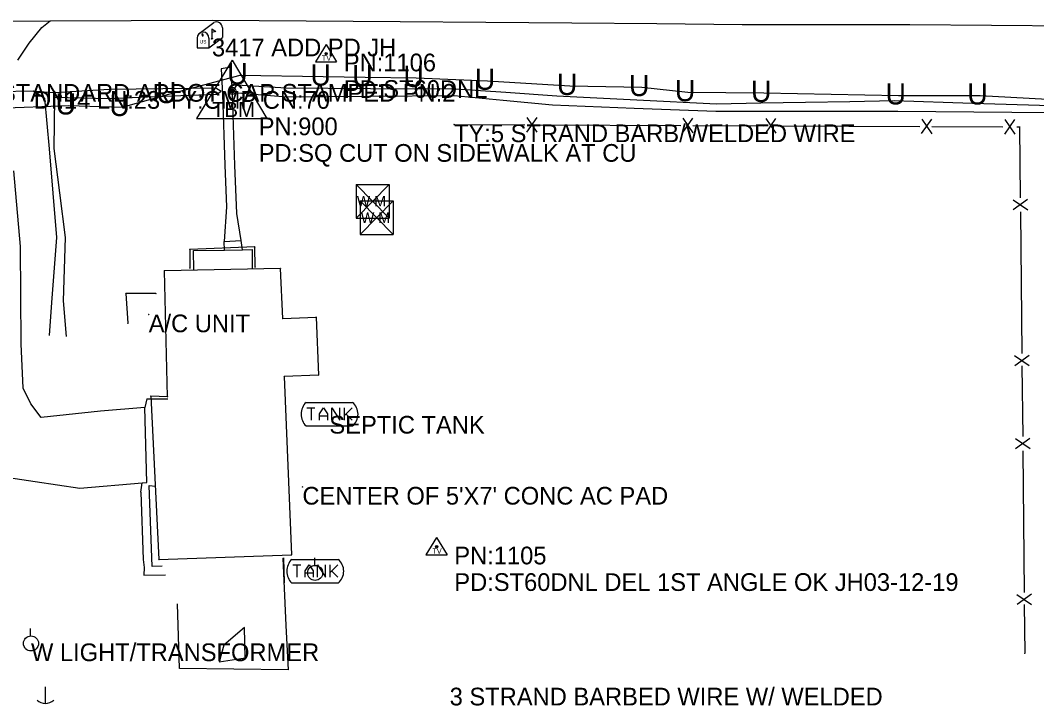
# Model space of a CAD drawing. Extents: x 1939239 to 1943096, y 531224 to 537447.
# Drawn here: x 1940013.5 to 1940300.4, y 534565.5 to 534758.9 of the extents above; entities that cross this region are included whole.
import ezdxf

# ---------------------------------------------------------------- set-up
doc = ezdxf.new("R2010")
doc.units = 0
for name, color, linetype in [('Default', 7, 'Continuous'), ('S_BUILDING', 7, 'Continuous'), ('S_DITCHLINE', 7, 'Continuous'), ('S_DRG_PT_SYM', 7, 'Continuous'), ('S_EDGE_BITUMINOUS', 7, 'Continuous'), ('S_EDGE_CONCRETE', 7, 'Continuous'), ('S_EDGE_PAVEMENT', 7, 'Continuous'), ('S_FENCE', 7, 'Continuous'), ('S_FENCE_ANNOT', 7, 'Continuous'), ('S_MAILBOX', 7, 'Continuous'), ('S_MAILBOX_ANNOT', 7, 'Continuous'), ('S_MISC_STRUCTURES_ANNOT', 7, 'Continuous'), ('S_MSC_PT_SYM', 7, 'Continuous'), ('S_PRIMARY_CTL', 7, 'Continuous'), ('S_PRIMARY_CTL_ANNOT', 7, 'Continuous'), ('S_SECONDARY_CTL', 7, 'Continuous'), ('S_SECONDARY_CTL_ANNOT', 7, 'Continuous'), ('S_SIDE_DRAIN', 7, 'Continuous'), ('S_SIDE_DRAIN_ANNOT', 7, 'Continuous'), ('S_STR_PT_SYM', 7, 'Continuous'), ('S_SURVEY_TEXT_ANNOT', 7, 'Continuous'), ('S_TANK', 7, 'Continuous'), ('S_TANK_ANNOT', 7, 'Continuous'), ('S_UNDERGROUND_CABLE', 7, 'Continuous'), ('S_UTILITY_POLE', 7, 'Continuous'), ('S_UTILITY_POLE_ANNOT', 7, 'Continuous'), ('S_WATER_UTILITIES', 7, 'Continuous')]:
    doc.layers.add(name, color=color, linetype=linetype)

msp = doc.modelspace()

# ---------------------------------------------------------------- linework, layer by layer
at = {"layer": 'S_BUILDING'}
for p, q in [((1940079.65, 534694.96), (1940061.33, 534694.27)), ((1940061.33, 534694.27), (1940061.34, 534688.97)), ((1940079.77, 534689.27), (1940079.65, 534694.96)), ((1940086.9, 534688.86), (1940054.18, 534688.24)), ((1940087.56, 534674.72), (1940086.9, 534688.86)), ((1940055.01, 534652.68), (1940054.18, 534688.24)), ((1940087.56, 534674.72), (1940097.03, 534675.12)), ((1940097.03, 534675.12), (1940097.62, 534658.8)), ((1940097.62, 534658.8), (1940088, 534658.34)), ((1940088, 534658.34), (1940090.03, 534608.07)), ((1940055.01, 534652.68), (1940050.31, 534652.79)), ((1940050.31, 534652.79), (1940052.6, 534606.75)), ((1940052.6, 534606.75), (1940090.03, 534608.07)), ((1940087.78, 534607.13), (1940087.96, 534600.22))]:
    msp.add_line(p, q, dxfattribs=at)
at = {"layer": 'S_DITCHLINE'}
for points in [[(1940073.52, 534739.02), (1940074.63, 534740.62)], [(1940304.36, 534734.79), (1940282.27, 534735.47), (1940260.17, 534736.16), (1940247.62, 534735.94), (1940235.08, 534735.72), (1940222.53, 534735.49), (1940209.99, 534735.27), (1940187.46, 534736.4), (1940164.92, 534737.53), (1940150.55, 534738.51), (1940136.18, 534739.48), (1940112.36, 534739.62), (1940088.54, 534739.76), (1940074.63, 534740.62)], [(1940070.18, 534738.87), (1940068.68, 534739.8), (1940053.68, 534739.61), (1940038.68, 534739.42), (1940023, 534738.45), (1940017.76, 534738.78), (1940020.31, 534736.94), (1940021.65, 534722.69), (1940022.69, 534710.15), (1940023.73, 534697.62), (1940022.3, 534679.3), (1940021.61, 534669.94)], [(1940068.92, 534738.02), (1940053.75, 534737.41), (1940038.58, 534736.8), (1940023.16, 534737.17), (1940022.94, 534722.76), (1940024.55, 534710.19), (1940026.16, 534697.63), (1940025.62, 534679.72), (1940026.41, 534669.71)], [(1940070.18, 534738.87), (1940068.92, 534738.02)], [(1940308.34, 534731.59), (1940304.08, 534732.82), (1940282.63, 534732.99), (1940261.17, 534733.15), (1940248.33, 534733.16), (1940235.49, 534733.17), (1940222.65, 534733.19), (1940209.81, 534733.2), (1940186.73, 534734.07), (1940163.66, 534734.95), (1940149.8, 534736.27), (1940135.95, 534737.58), (1940112.32, 534737.41), (1940088.69, 534737.23), (1940074.89, 534738.4), (1940073.52, 534739.02)]]:
    msp.add_lwpolyline(points, dxfattribs=at)
at = {"layer": 'S_DRG_PT_SYM'}
msp.add_lwpolyline([(1940017.28, 534738.95), (1940017.28, 534739), (1940017.28, 534738.95), (1940017.23, 534738.95), (1940017.28, 534738.95), (1940017.28, 534738.9), (1940017.28, 534738.95), (1940017.33, 534738.95)], dxfattribs=at)
at = {"layer": 'S_EDGE_BITUMINOUS'}
for points in [[(1940019.56, 534756.91), (1940021.94, 534758.77)], [(1940012.8, 534747.64), (1940016.02, 534752.51), (1940019.56, 534756.91)], [(1940005.08, 534630.66), (1940017.69, 534628.78), (1940030.3, 534626.9), (1940047.87, 534628.35), (1940049.22, 534628.48), (1940048.63, 534649.66), (1940036.14, 534648.56), (1940019.33, 534646.84), (1940016.44, 534650.71), (1940014.31, 534655.04), (1940013.77, 534667.59), (1940013.67, 534681.32), (1940013.57, 534695.05), (1940011.68, 534716.45)]]:
    msp.add_lwpolyline(points, dxfattribs=at)
at = {"layer": 'S_EDGE_CONCRETE'}
for points in [[(1940071.02, 534696.5), (1940075.83, 534696.77), (1940074.62, 534704.38), (1940073.99, 534718.08), (1940073.4, 534737.79), (1940073.02, 534745.71), (1940070.16, 534745.24), (1940070.54, 534737.96), (1940071.17, 534718.03), (1940071.7, 534706.3)], [(1940076.8, 534587.56), (1940070.96, 534582.54), (1940069.65, 534577.86), (1940076.99, 534578.99)]]:
    msp.add_lwpolyline(points, close=True, dxfattribs=at)
for points in [[(1940062.42, 534688.53), (1940062.38, 534693.99), (1940071.12, 534694.07), (1940076.16, 534694.15), (1940078.91, 534694.22), (1940078.89, 534688.76)], [(1940071.12, 534694.07), (1940071.02, 534696.5)], [(1940076.16, 534694.15), (1940075.83, 534696.77)], [(1940049.2, 534652.05), (1940048.63, 534649.66)], [(1940049.2, 534652.05), (1940055.11, 534652.03)], [(1940047.53, 534625.71), (1940047.87, 534628.35)], [(1940047.53, 534625.71), (1940048.19, 534606.71), (1940048.4, 534604.44), (1940048.34, 534602.31), (1940054.5, 534602.43)], [(1940053.5, 534604.86), (1940050.72, 534604.79), (1940049.81, 534627.6), (1940051.67, 534627.44)], [(1940087.56, 534607.13), (1940087.82, 534600.66), (1940088.44, 534588.13), (1940089.06, 534575.6), (1940073.76, 534575.79), (1940058.46, 534575.98), (1940057.82, 534594.2)]]:
    msp.add_lwpolyline(points, dxfattribs=at)
at = {"layer": 'S_EDGE_PAVEMENT'}
for points in [[(1939991.5, 534758.52), (1940006.72, 534758.65), (1940021.94, 534758.77)], [(1940021.94, 534758.77), (1940044.8, 534758.84), (1940067.66, 534758.92), (1940080.92, 534758.84), (1940094.18, 534758.75), (1940107.43, 534758.67), (1940120.69, 534758.58), (1940144.9, 534758.41), (1940169.11, 534758.24), (1940193.16, 534758.01), (1940217.21, 534757.78), (1940240.86, 534757.78), (1940264.51, 534757.78), (1940287.59, 534757.58), (1940310.67, 534757.37)]]:
    msp.add_lwpolyline(points, dxfattribs=at)
at = {"layer": 'S_FENCE'}
for p, q in [((1940156.45, 534727.39), (1940159.34, 534731.48)), ((1940156.45, 534727.39), (1940159.34, 534731.48)), ((1940156.47, 534731.49), (1940159.32, 534727.38)), ((1940156.47, 534731.49), (1940159.32, 534727.38)), ((1940200.45, 534727.21), (1940203.34, 534731.29)), ((1940200.45, 534727.21), (1940203.34, 534731.29)), ((1940200.47, 534731.3), (1940203.32, 534727.2)), ((1940200.47, 534731.3), (1940203.32, 534727.2)), ((1940223.89, 534727.11), (1940226.77, 534731.19)), ((1940223.89, 534727.11), (1940226.77, 534731.19)), ((1940223.9, 534731.21), (1940226.75, 534727.1)), ((1940223.9, 534731.21), (1940226.75, 534727.1)), ((1940267.89, 534726.93), (1940270.77, 534731.01)), ((1940267.89, 534726.93), (1940270.77, 534731.01)), ((1940267.9, 534731.02), (1940270.75, 534726.91)), ((1940267.9, 534731.02), (1940270.75, 534726.91)), ((1940291.32, 534726.83), (1940294.2, 534730.91)), ((1940291.32, 534726.83), (1940294.2, 534730.91)), ((1940291.34, 534730.92), (1940294.19, 534726.82)), ((1940291.34, 534730.92), (1940294.19, 534726.82)), ((1940293.69, 534708.27), (1940297.82, 534705.45)), ((1940293.69, 534708.27), (1940297.82, 534705.45)), ((1940297.79, 534708.31), (1940293.72, 534705.4)), ((1940297.79, 534708.31), (1940293.72, 534705.4)), ((1940294.12, 534664.28), (1940298.25, 534661.45)), ((1940294.12, 534664.28), (1940298.25, 534661.45)), ((1940298.22, 534664.32), (1940294.15, 534661.41)), ((1940298.22, 534664.32), (1940294.15, 534661.41)), ((1940294.35, 534640.84), (1940298.48, 534638.02)), ((1940294.35, 534640.84), (1940298.48, 534638.02)), ((1940298.45, 534640.88), (1940294.38, 534637.97)), ((1940298.45, 534640.88), (1940294.38, 534637.97)), ((1940294.79, 534596.85), (1940298.91, 534594.02)), ((1940294.79, 534596.85), (1940298.91, 534594.02)), ((1940298.88, 534596.89), (1940294.82, 534593.98)), ((1940298.88, 534596.89), (1940294.82, 534593.98))]:
    msp.add_line(p, q, dxfattribs=at)
for points in [[(1940135.9, 534729.53), (1940155.9, 534729.44)], [(1940135.9, 534729.53), (1940155.9, 534729.44)], [(1940159.9, 534729.43), (1940199.9, 534729.26)], [(1940159.9, 534729.43), (1940199.9, 534729.26)], [(1940203.33, 534729.24), (1940223.33, 534729.16)], [(1940203.33, 534729.24), (1940223.33, 534729.16)], [(1940227.33, 534729.14), (1940267.33, 534728.98)], [(1940227.33, 534729.14), (1940267.33, 534728.98)], [(1940270.76, 534728.96), (1940290.76, 534728.88)], [(1940270.76, 534728.96), (1940290.76, 534728.88)], [(1940294.76, 534728.86), (1940295.54, 534728.86)], [(1940294.76, 534728.86), (1940295.54, 534728.86)], [(1940295.54, 534728.86), (1940295.73, 534708.86)], [(1940295.54, 534728.86), (1940295.73, 534708.86)], [(1940295.77, 534704.86), (1940296.17, 534664.86)], [(1940295.77, 534704.86), (1940296.17, 534664.86)], [(1940051.78, 534681.8), (1940043.28, 534681.79)], [(1940051.78, 534681.8), (1940043.28, 534681.79)], [(1940043.28, 534681.79), (1940043.85, 534673.4)], [(1940043.28, 534681.79), (1940043.85, 534673.4)], [(1940296.2, 534661.43), (1940296.4, 534641.43)], [(1940296.2, 534661.43), (1940296.4, 534641.43)], [(1940296.44, 534637.43), (1940296.83, 534597.43)], [(1940296.44, 534637.43), (1940296.83, 534597.43)], [(1940296.86, 534594), (1940297, 534580.26)], [(1940296.86, 534594), (1940297, 534580.26)]]:
    msp.add_lwpolyline(points, dxfattribs=at)
at = {"layer": 'S_MAILBOX'}
for p, q in [((1940063.96, 534755.19), (1940068.09, 534758.3)), ((1940067.58, 534756.48), (1940067.58, 534753.76)), ((1940070.53, 534756.82), (1940070.53, 534754.11)), ((1940063.41, 534753.91), (1940063.41, 534751.2)), ((1940066.73, 534751.2), (1940070.53, 534754.11)), ((1940066.73, 534753.91), (1940066.73, 534751.2)), ((1940063.41, 534751.2), (1940066.73, 534751.2))]:
    msp.add_line(p, q, dxfattribs=at)
for points in [[(1940064.59, 534755.03), (1940064.81, 534754.89), (1940064.81, 534754.5), (1940065.12, 534754.5), (1940065.12, 534754.86), (1940064.92, 534755.11), (1940064.59, 534755.06)], [(1940067.58, 534756.48), (1940068.68, 534755.81), (1940067.58, 534755.47)]]:
    msp.add_lwpolyline(points, dxfattribs=at)
for centre, end in [((1940068.86, 534756.82), 117.5718), ((1940065.07, 534753.91), 180)]:
    msp.add_arc(centre, 1.66, 0, end, dxfattribs=at)
msp.add_ellipse((1940067.58, 534753.76), major_axis=(0.145, 0.132), ratio=0.564646, dxfattribs=at)
at = {"layer": 'S_MSC_PT_SYM'}
for points in [[(1940135.9, 534729.53), (1940135.9, 534729.58), (1940135.9, 534729.53), (1940135.85, 534729.53), (1940135.9, 534729.53), (1940135.9, 534729.48), (1940135.9, 534729.53), (1940135.95, 534729.53)], [(1940295.54, 534728.86), (1940295.54, 534728.91), (1940295.54, 534728.86), (1940295.49, 534728.86), (1940295.54, 534728.86), (1940295.54, 534728.81), (1940295.54, 534728.86), (1940295.59, 534728.86)], [(1940043.28, 534681.79), (1940043.28, 534681.84), (1940043.28, 534681.79), (1940043.23, 534681.79), (1940043.28, 534681.79), (1940043.28, 534681.74), (1940043.28, 534681.79), (1940043.33, 534681.79)], [(1940051.78, 534681.8), (1940051.78, 534681.85), (1940051.78, 534681.8), (1940051.73, 534681.8), (1940051.78, 534681.8), (1940051.78, 534681.75), (1940051.78, 534681.8), (1940051.83, 534681.8)], [(1940049.73, 534675.87), (1940049.73, 534675.92), (1940049.73, 534675.87), (1940049.68, 534675.87), (1940049.73, 534675.87), (1940049.73, 534675.82), (1940049.73, 534675.87), (1940049.78, 534675.87)], [(1940043.85, 534673.4), (1940043.85, 534673.45), (1940043.85, 534673.4), (1940043.8, 534673.4), (1940043.85, 534673.4), (1940043.85, 534673.35), (1940043.85, 534673.4), (1940043.9, 534673.4)], [(1940093.11, 534627.22), (1940093.11, 534627.27), (1940093.11, 534627.22), (1940093.06, 534627.22), (1940093.11, 534627.22), (1940093.11, 534627.17), (1940093.11, 534627.22), (1940093.16, 534627.22)], [(1940297, 534580.26), (1940297, 534580.31), (1940297, 534580.26), (1940296.95, 534580.26), (1940297, 534580.26), (1940297, 534580.21), (1940297, 534580.26), (1940297.05, 534580.26)]]:
    msp.add_lwpolyline(points, dxfattribs=at)
at = {"layer": 'S_PRIMARY_CTL'}
for p, q in [((1940073.27, 534747.69), (1940063.23, 534731.18)), ((1940073.27, 534747.69), (1940083.09, 534731.18)), ((1940063.23, 534731.18), (1940083.09, 534731.18))]:
    msp.add_line(p, q, dxfattribs=at)
for radius in [1.04, 0.609, 0.344]:
    msp.add_circle((1940073.27, 534738.99), radius, dxfattribs=at)
at = {"layer": 'S_SECONDARY_CTL'}
for p, q in [((1940099.8, 534752.13), (1940096.79, 534747.18)), ((1940099.8, 534752.13), (1940102.75, 534747.18)), ((1940096.79, 534747.18), (1940102.75, 534747.18)), ((1940130.98, 534612.96), (1940127.97, 534608.01)), ((1940130.98, 534612.96), (1940133.93, 534608.01)), ((1940127.97, 534608.01), (1940133.93, 534608.01))]:
    msp.add_line(p, q, dxfattribs=at)
for centre, radius in [((1940099.8, 534749.52), 0.311), ((1940099.8, 534749.52), 0.183), ((1940099.8, 534749.52), 0.103), ((1940130.98, 534610.35), 0.311), ((1940130.98, 534610.35), 0.183), ((1940130.98, 534610.35), 0.103)]:
    msp.add_circle(centre, radius, dxfattribs=at)
at = {"layer": 'S_SIDE_DRAIN'}
msp.add_line((1940017.28, 534738.95), (1939993.92, 534738.5), dxfattribs=at)
at = {"layer": 'S_STR_PT_SYM'}
for points in [[(1940061.33, 534694.27), (1940061.33, 534694.32), (1940061.33, 534694.27), (1940061.28, 534694.27), (1940061.33, 534694.27), (1940061.33, 534694.22), (1940061.33, 534694.27), (1940061.38, 534694.27)], [(1940079.65, 534694.96), (1940079.65, 534695.01), (1940079.65, 534694.96), (1940079.6, 534694.96), (1940079.65, 534694.96), (1940079.65, 534694.91), (1940079.65, 534694.96), (1940079.7, 534694.96)], [(1940061.34, 534688.97), (1940061.34, 534689.02), (1940061.34, 534688.97), (1940061.29, 534688.97), (1940061.34, 534688.97), (1940061.34, 534688.92), (1940061.34, 534688.97), (1940061.39, 534688.97)], [(1940079.77, 534689.27), (1940079.77, 534689.32), (1940079.77, 534689.27), (1940079.72, 534689.27), (1940079.77, 534689.27), (1940079.77, 534689.22), (1940079.77, 534689.27), (1940079.82, 534689.27)], [(1940086.9, 534688.86), (1940086.9, 534688.91), (1940086.9, 534688.86), (1940086.85, 534688.86), (1940086.9, 534688.86), (1940086.9, 534688.81), (1940086.9, 534688.86), (1940086.95, 534688.86)], [(1940054.18, 534688.24), (1940054.18, 534688.29), (1940054.18, 534688.24), (1940054.13, 534688.24), (1940054.18, 534688.24), (1940054.18, 534688.19), (1940054.18, 534688.24), (1940054.23, 534688.24)], [(1940087.56, 534674.72), (1940087.56, 534674.77), (1940087.56, 534674.72), (1940087.51, 534674.72), (1940087.56, 534674.72), (1940087.56, 534674.67), (1940087.56, 534674.72), (1940087.61, 534674.72)], [(1940097.03, 534675.12), (1940097.03, 534675.18), (1940097.03, 534675.12), (1940096.98, 534675.12), (1940097.03, 534675.12), (1940097.03, 534675.07), (1940097.03, 534675.12), (1940097.08, 534675.12)], [(1940088, 534658.34), (1940088, 534658.39), (1940088, 534658.34), (1940087.95, 534658.34), (1940088, 534658.34), (1940088, 534658.29), (1940088, 534658.34), (1940088.05, 534658.34)], [(1940097.62, 534658.8), (1940097.62, 534658.85), (1940097.62, 534658.8), (1940097.57, 534658.8), (1940097.62, 534658.8), (1940097.62, 534658.75), (1940097.62, 534658.8), (1940097.67, 534658.8)], [(1940050.31, 534652.79), (1940050.31, 534652.84), (1940050.31, 534652.79), (1940050.26, 534652.79), (1940050.31, 534652.79), (1940050.31, 534652.74), (1940050.31, 534652.79), (1940050.36, 534652.79)], [(1940055.01, 534652.68), (1940055.01, 534652.73), (1940055.01, 534652.68), (1940054.96, 534652.68), (1940055.01, 534652.68), (1940055.01, 534652.63), (1940055.01, 534652.68), (1940055.06, 534652.68)], [(1940052.6, 534606.75), (1940052.6, 534606.8), (1940052.6, 534606.75), (1940052.55, 534606.75), (1940052.6, 534606.75), (1940052.6, 534606.7), (1940052.6, 534606.75), (1940052.65, 534606.75)], [(1940087.78, 534607.13), (1940087.78, 534607.18), (1940087.78, 534607.13), (1940087.73, 534607.13), (1940087.78, 534607.13), (1940087.78, 534607.08), (1940087.78, 534607.13), (1940087.83, 534607.13)], [(1940090.03, 534608.07), (1940090.03, 534608.12), (1940090.03, 534608.07), (1940089.98, 534608.07), (1940090.03, 534608.07), (1940090.03, 534608.02), (1940090.03, 534608.07), (1940090.08, 534608.07)], [(1940087.96, 534600.22), (1940087.96, 534600.27), (1940087.96, 534600.22), (1940087.91, 534600.22), (1940087.96, 534600.22), (1940087.96, 534600.17), (1940087.96, 534600.22), (1940088.01, 534600.22)]]:
    msp.add_lwpolyline(points, dxfattribs=at)
at = {"layer": 'S_TANK'}
for p, q in [((1940094.14, 534651.07), (1940107.25, 534651.07)), ((1940094.4, 534649.58), (1940096.66, 534649.58)), ((1940095.56, 534649.58), (1940095.56, 534646.1)), ((1940097.89, 534647.84), (1940099.05, 534649.58)), ((1940099.05, 534649.58), (1940100.15, 534647.84)), ((1940101.38, 534646.1), (1940101.38, 534649.58)), ((1940101.38, 534649.58), (1940103.64, 534646.1)), ((1940103.64, 534646.1), (1940103.64, 534649.58)), ((1940104.86, 534649.58), (1940104.86, 534646.1)), ((1940104.86, 534647.26), (1940107.12, 534649.58)), ((1940097.89, 534646.1), (1940097.89, 534647.84)), ((1940100.15, 534647.19), (1940097.89, 534647.19)), ((1940100.15, 534647.84), (1940100.15, 534646.1)), ((1940105.44, 534647.77), (1940107.12, 534646.1)), ((1940094.14, 534644.42), (1940107.25, 534644.42)), ((1940090.11, 534606.74), (1940103.22, 534606.74)), ((1940090.36, 534605.26), (1940092.62, 534605.26)), ((1940091.53, 534605.26), (1940091.53, 534601.77)), ((1940093.85, 534603.51), (1940095.01, 534605.26)), ((1940095.01, 534605.26), (1940096.11, 534603.51)), ((1940097.34, 534601.77), (1940097.34, 534605.26)), ((1940097.34, 534605.26), (1940099.6, 534601.77)), ((1940099.6, 534601.77), (1940099.6, 534605.26)), ((1940100.83, 534605.26), (1940100.83, 534601.77)), ((1940100.83, 534602.93), (1940103.09, 534605.26)), ((1940093.85, 534601.77), (1940093.85, 534603.51)), ((1940096.11, 534602.87), (1940093.85, 534602.87)), ((1940096.11, 534603.51), (1940096.11, 534601.77)), ((1940101.41, 534603.45), (1940103.09, 534601.77)), ((1940090.11, 534600.09), (1940103.22, 534600.09))]:
    msp.add_line(p, q, dxfattribs=at)
for centre, radius, start, end in [((1940097.32, 534647.74), 4.6, 133.7339, 226.2661), ((1940104.46, 534647.74), 4.34, 309.9965, 50.0035), ((1940093.29, 534603.41), 4.6, 133.7339, 226.2661), ((1940100.43, 534603.41), 4.34, 309.9965, 50.0035)]:
    msp.add_arc(centre, radius, start, end, dxfattribs=at)
at = {"layer": 'S_UNDERGROUND_CABLE'}
for p, q in [((1940055.45, 534738.1), (1940075.51, 534743.41)), ((1940075.51, 534743.41), (1940099.01, 534743.04)), ((1940099.01, 534743.04), (1940110.8, 534742.89)), ((1940110.8, 534742.89), (1940125.22, 534742.65)), ((1940125.22, 534742.65), (1940145.39, 534741.85)), ((1940145.39, 534741.85), (1940168.55, 534740.39)), ((1940168.55, 534740.39), (1940188.9, 534740.07)), ((1940042.24, 534734.44), (1940055.45, 534738.1)), ((1940188.9, 534740.07), (1940201.86, 534738.63)), ((1940201.86, 534738.63), (1940223.34, 534738.41)), ((1940223.34, 534738.41), (1940261.31, 534737.72)), ((1940261.31, 534737.72), (1940284.37, 534737.7)), ((1940284.37, 534737.7), (1940322.64, 534735.65)), ((1939999.47, 534733.87), (1940027.08, 534734.89)), ((1940027.08, 534734.89), (1940042.24, 534734.44))]:
    msp.add_line(p, q, dxfattribs=at)
at = {"layer": 'S_UTILITY_POLE'}
for p, q in [((1940096.57, 534605.07), (1940096.57, 534607.18)), ((1940016.38, 534585.17), (1940016.38, 534587.28)), ((1940020.51, 534570.79), (1940020.51, 534566.07))]:
    msp.add_line(p, q, dxfattribs=at)
for centre in [(1940096.69, 534602.93), (1940016.5, 534583.03)]:
    msp.add_circle(centre, 2.13, dxfattribs=at)
msp.add_arc((1940020.57, 534569.49), 3.41, 226.3972, 313.6028, dxfattribs=at)
at = {"layer": 'S_WATER_UTILITIES'}
for p, q in [((1940108.27, 534712.6), (1940117.61, 534712.6)), ((1940108.27, 534712.6), (1940108.27, 534703.11)), ((1940108.27, 534712.6), (1940117.61, 534703.11)), ((1940117.61, 534712.6), (1940108.27, 534703.11)), ((1940117.61, 534712.6), (1940117.61, 534703.11)), ((1940109.42, 534707.93), (1940118.76, 534707.93)), ((1940109.42, 534707.93), (1940109.42, 534698.43)), ((1940109.42, 534707.93), (1940118.76, 534698.43)), ((1940118.76, 534707.93), (1940109.42, 534698.43)), ((1940118.76, 534707.93), (1940118.76, 534698.43)), ((1940108.27, 534703.11), (1940117.61, 534703.11)), ((1940109.42, 534698.43), (1940118.76, 534698.43))]:
    msp.add_line(p, q, dxfattribs=at)

# ---------------------------------------------------------------- texts
at = {"layer": 'Default'}
for p in [(1940071.88, 534740.86), (1940095.38, 534740.49), (1940107.17, 534740.34), (1940121.59, 534740.11), (1940141.76, 534739.31), (1940164.92, 534737.84), (1940185.27, 534737.53), (1940051.82, 534735.55), (1940198.23, 534736.08), (1940219.71, 534735.86), (1940257.68, 534735.17), (1940280.74, 534735.16), (1940023.45, 534732.34), (1940038.61, 534731.9)]:
    msp.add_text('U', height=6, dxfattribs=at).set_placement(p)
at = {"layer": 'S_FENCE_ANNOT'}
for s, p in [('TY:5 STRAND BARB/WELDED WIRE', (1940135.9, 534724.53)), ('3 STRAND BARBED WIRE W/ WELDED ', (1940134.67, 534565.53))]:
    msp.add_text(s, height=5, dxfattribs=at).set_placement(p)
at = {"layer": 'S_MAILBOX'}
msp.add_text('US', height=0.96, dxfattribs=at).set_placement((1940064.17, 534752.39))
at = {"layer": 'S_MAILBOX_ANNOT'}
msp.add_text('3417 ADD PD JH', height=5, dxfattribs=at).set_placement((1940067.58, 534748.76))
at = {"layer": 'S_MISC_STRUCTURES_ANNOT'}
msp.add_text('A/C UNIT', height=5, dxfattribs=at).set_placement((1940049.73, 534670.87))
at = {"layer": 'S_PRIMARY_CTL'}
msp.add_text('TBM', height=4.287, dxfattribs=at).set_placement((1940067.61, 534731.6))
at = {"layer": 'S_PRIMARY_CTL_ANNOT'}
for s, p in [('PD:STANDARD ARDOT CAP STAMPED PN:2', (1939996.61, 534735.95)), ('PN:900', (1940080.77, 534726.49)), ('PD:SQ CUT ON SIDEWALK AT CU', (1940080.77, 534718.99))]:
    msp.add_text(s, height=5, dxfattribs=at).set_placement(p)
at = {"layer": 'S_SECONDARY_CTL'}
for p in [(1940098.6, 534747.51), (1940129.78, 534608.34)]:
    msp.add_text('TV', height=1.5, dxfattribs=at).set_placement(p)
at = {"layer": 'S_SECONDARY_CTL_ANNOT'}
for s, p in [('PN:1106', (1940104.8, 534744.52)), ('PD:ST60DNL', (1940104.8, 534737.02)), ('PN:1105', (1940135.98, 534605.35)), ('PD:ST60DNL DEL 1ST ANGLE OK JH03-12-19', (1940135.98, 534597.85))]:
    msp.add_text(s, height=5, dxfattribs=at).set_placement(p)
at = {"layer": 'S_SIDE_DRAIN_ANNOT'}
msp.add_text('DI:14 LN:23 TY:CMP CN:70', height=5, dxfattribs=at).set_placement((1940017.28, 534733.95))
at = {"layer": 'S_SURVEY_TEXT_ANNOT'}
msp.add_text("CENTER OF 5'X7' CONC AC PAD", height=5, dxfattribs=at).set_placement((1940093.11, 534622.22))
at = {"layer": 'S_TANK_ANNOT'}
msp.add_text('SEPTIC TANK', height=5, dxfattribs=at).set_placement((1940100.73, 534642.26))
at = {"layer": 'S_UTILITY_POLE_ANNOT'}
msp.add_text('W LIGHT/TRANSFORMER', height=5, dxfattribs=at).set_placement((1940016.5, 534578.03))
at = {"layer": 'S_WATER_UTILITIES'}
for p in [(1940108.47, 534706.37), (1940109.62, 534701.69)]:
    msp.add_text('W M', height=3, dxfattribs=at).set_placement(p)

doc.saveas('drawing.dxf')
